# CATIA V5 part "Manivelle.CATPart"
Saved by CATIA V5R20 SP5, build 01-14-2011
Part number: Manivelle
Bounding box of the stored display mesh (mm): x -9.997 to 16, y -42 to 8.288, z -9.997 to 9.997
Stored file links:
  D:\Dropbox\IAO_2011\MMS_GR1\dwalter\dwalter\CATIA\Manivelle.CATPart
  D:\Dropbox\IAO_2011\MMS_GR1\dwalter\dwalter\CATIA\dwalter.CATProduct
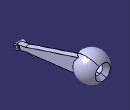
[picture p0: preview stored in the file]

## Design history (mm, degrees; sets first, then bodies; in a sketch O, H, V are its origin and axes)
Set1
  Plane1: linked copy from another document
  Point1: linked copy from another document
  Line1: linked copy from another document
  Plane2: linked copy from another document
  Line2: linked copy from another document
  Plane3: linked copy from another document
  Plane4: linked copy from another document
Body1 (main body)
  Sketch1 on Plane1, origin (0, 0, 0), H (0, 1, 0), V (0, 0, 1)
    arc A1 centre (0, 0) radius 10 from (8.2885, 5.5948) to (-8.2885, 5.5948) ccw
    point P1 (0, 0)
    arc A2 centre (0, 0) radius 6 from (5.1962, 3) to (-5.1962, 3) ccw
    point P4 (0, 0)
    point P5 (5.1962, 3)
    point P6 (-5.1962, 3)
    reference projected point E1 (0, 0) from Point1
    reference projected point E2 (0, 0) from Point1
    line L1 (5.1962, 3) -> (8.2885, 5.5948)
    line L2 (-5.1962, 3) -> (-8.2885, 5.5948)
    reference projected line E3 (0, 0) -> (-40, 0) from Line1
    reference projected line E4 (0, 0) -> (-40, 0) from Line1
    radius A1 = 10
    radius A2 = 6
    angle L2 E3 = 40
    angle L1 E4 = 40
    distance P5 H = 3
    coincidence: P4 E1, P1 E2
    symmetry: P6 P5 V
  Shaft1: profile Sketch1, axis Line2, angle 360
  Sketch2 on Plane4, origin (3.8806, 0.9701, 0), H (0.2425, -0.9701, 0), V (0, 0, 1)
    line L1 (5, -4) -> (5, 7)
    line L2 (5, 7) -> (37, 2)
    line L3 (37, 2) -> (37, -1)
    line L4 (37, -1) -> (5, -4)
    vertical: L1 V, L3 V
  Pad1: profile Sketch2, direction (0.9701, 0.2425, 0), length 1.8, mirrored extent
  Sketch3 on Plane2, origin (10, 0, 0), H (0, 1, 0), V (0, 0, 1)
    circle A1 centre (-40, 0) radius 1
    point P1 (-40, 0)
    circle A2 centre (-40, 0) radius 2
    point P2 (-40, 0)
    reference projected line E1 (0, 0) -> (-40, 0) from Line1
    reference projected point E2 (0, 0) from Point1
    distance E2 P1 = 40
    radius A2 = 2
    radius A1 = 1
    coincidence: P2 P1, P2 E1
  Pad2: profile Sketch3, direction (1, 0, 0), length 6
  Sketch4 on face of Pad1 from Sketch2.L3, origin (8.9738, -35.8953, 0), H (0.9701, 0.2425, 0), V (0, 0, 1)
  Pad3: profile Sketch4, direction (0.2425, -0.9701, 0), up to face of Pad2 from Sketch3.A2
